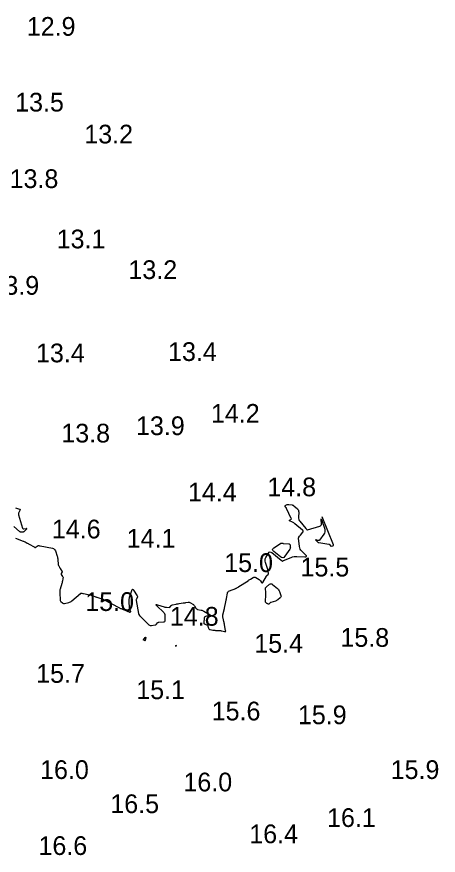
# Model space of a CAD drawing. Extents: x 3040093 to 3056816, y 408076 to 509144.
# Drawn here: x 3044913.4 to 3045025.9, y 434993.4 to 435217.4 of the extents above; entities that cross this region are included whole.
import ezdxf

# ---------------------------------------------------------------- set-up
doc = ezdxf.new("R2010")
doc.units = 0
doc.layers.add('V-CHAN-CONT-EL15', color=7, linetype='Continuous')
doc.layers.add('V-TOPO-SOUN-0810', color=7, linetype='Continuous')

msp = doc.modelspace()

# ---------------------------------------------------------------- linework, layer by layer
at = {"layer": 'V-CHAN-CONT-EL15'}
for points in [[(3044913.02, 435086.15), (3044914.08, 435085.86), (3044914.21, 435085.8), (3044914.27, 435085.72), (3044914.28, 435085.62), (3044914.23, 435085.49), (3044913.9, 435084.93), (3044913.83, 435084.79), (3044913.8, 435084.64), (3044913.8, 435084.49), (3044913.83, 435084.34), (3044914.91, 435080.78), (3044914.97, 435080.66), (3044915.05, 435080.58), (3044915.15, 435080.55), (3044915.29, 435080.56), (3044915.86, 435080.68), (3044915.98, 435080.7), (3044916.03, 435080.67), (3044916.02, 435080.62), (3044915.96, 435080.52), (3044915.4, 435079.87), (3044915.31, 435079.79), (3044915.21, 435079.73), (3044915.11, 435079.7), (3044914.99, 435079.69), (3044914.49, 435079.69), (3044914.38, 435079.7), (3044914.26, 435079.73), (3044914.16, 435079.78), (3044914.07, 435079.85), (3044912.58, 435081.21)], [(3044913.08, 435078.05), (3044915.08, 435077.3), (3044915.21, 435077.25), (3044915.35, 435077.19), (3044915.49, 435077.13), (3044915.62, 435077.06), (3044916.14, 435076.78), (3044916.27, 435076.71), (3044916.4, 435076.64), (3044916.53, 435076.57), (3044916.66, 435076.49), (3044918.06, 435075.72), (3044918.08, 435075.71), (3044918.1, 435075.7), (3044918.12, 435075.69), (3044918.14, 435075.68), (3044918.21, 435075.63), (3044918.22, 435075.62), (3044918.24, 435075.61), (3044918.26, 435075.62), (3044918.28, 435075.62), (3044919.12, 435076.08), (3044919.16, 435076.1), (3044919.2, 435076.11), (3044919.25, 435076.11), (3044919.3, 435076.1), (3044919.48, 435076.05), (3044919.53, 435076.04), (3044919.58, 435076.03), (3044919.62, 435076.02), (3044919.67, 435076.01), (3044922.88, 435075.39), (3044923.17, 435075.3), (3044923.4, 435075.15), (3044923.58, 435074.94), (3044923.71, 435074.66), (3044924.16, 435073.31), (3044924.23, 435073.07), (3044924.29, 435072.83), (3044924.33, 435072.59), (3044924.35, 435072.34), (3044924.45, 435071.06), (3044924.46, 435070.96), (3044924.49, 435070.87), (3044924.52, 435070.78), (3044924.57, 435070.69), (3044924.77, 435070.34), (3044924.82, 435070.26), (3044924.88, 435070.17), (3044924.93, 435070.09), (3044924.98, 435070), (3044925.44, 435069.23), (3044925.47, 435069.15), (3044925.48, 435069.08), (3044925.47, 435069.01), (3044925.43, 435068.94), (3044925.26, 435068.65), (3044925.23, 435068.58), (3044925.22, 435068.51), (3044925.23, 435068.44), (3044925.26, 435068.37), (3044925.63, 435067.82), (3044925.69, 435067.71), (3044925.73, 435067.58), (3044925.74, 435067.46), (3044925.72, 435067.33), (3044925.57, 435066.63), (3044925.54, 435066.47), (3044925.5, 435066.31), (3044925.46, 435066.15), (3044925.41, 435066), (3044924.94, 435064.41), (3044924.92, 435064.31), (3044924.9, 435064.22), (3044924.89, 435064.12), (3044924.89, 435064.03), (3044924.89, 435063.64), (3044924.89, 435063.54), (3044924.9, 435063.45), (3044924.9, 435063.35), (3044924.9, 435063.25), (3044924.95, 435061.67), (3044924.97, 435061.53), (3044925.01, 435061.4), (3044925.08, 435061.28), (3044925.18, 435061.17), (3044925.6, 435060.76), (3044925.71, 435060.67), (3044925.83, 435060.62), (3044925.96, 435060.6), (3044926.1, 435060.62), (3044927.27, 435060.91), (3044927.5, 435060.98), (3044927.72, 435061.08), (3044927.93, 435061.2), (3044928.13, 435061.35), (3044930.4, 435063.32), (3044930.42, 435063.34), (3044930.45, 435063.36), (3044930.48, 435063.37), (3044930.51, 435063.37), (3044930.63, 435063.39), (3044930.66, 435063.39), (3044930.69, 435063.39), (3044930.72, 435063.39), (3044930.75, 435063.38), (3044931.02, 435063.3), (3044931.07, 435063.29), (3044931.13, 435063.27), (3044931.18, 435063.26), (3044931.24, 435063.25), (3044933.22, 435062.81), (3044933.35, 435062.78), (3044933.48, 435062.75), (3044933.61, 435062.71), (3044933.74, 435062.66), (3044934.24, 435062.47), (3044934.37, 435062.43), (3044934.5, 435062.39), (3044934.63, 435062.34), (3044934.76, 435062.3), (3044935.84, 435061.99), (3044936.06, 435061.92), (3044936.28, 435061.84), (3044936.49, 435061.74), (3044936.7, 435061.64), (3044940.65, 435059.53), (3044940.79, 435059.46), (3044940.93, 435059.39), (3044941.08, 435059.33), (3044941.22, 435059.28), (3044941.83, 435059.06), (3044941.97, 435059.02), (3044942.1, 435058.96), (3044942.24, 435058.91), (3044942.37, 435058.85), (3044943.07, 435058.52), (3044943.12, 435058.5), (3044943.16, 435058.48), (3044943.2, 435058.46), (3044943.24, 435058.45), (3044943.41, 435058.38), (3044943.46, 435058.36), (3044943.5, 435058.35), (3044943.55, 435058.35), (3044943.59, 435058.35), (3044943.81, 435058.36), (3044943.85, 435058.37), (3044943.88, 435058.39), (3044943.88, 435058.42), (3044943.87, 435058.46), (3044943.6, 435058.95), (3044943.55, 435059.05), (3044943.52, 435059.16), (3044943.5, 435059.26), (3044943.48, 435059.37), (3044943.39, 435061.28), (3044943.39, 435061.38), (3044943.39, 435061.49), (3044943.4, 435061.6), (3044943.42, 435061.71), (3044943.48, 435062.15), (3044943.5, 435062.25), (3044943.52, 435062.36), (3044943.55, 435062.47), (3044943.58, 435062.57), (3044944.09, 435064.11), (3044944.2, 435064.33), (3044944.32, 435064.41), (3044944.45, 435064.36), (3044944.6, 435064.17), (3044945.55, 435062.64), (3044945.59, 435062.53), (3044945.61, 435062.43), (3044945.6, 435062.33), (3044945.55, 435062.23), (3044945.32, 435061.82), (3044945.27, 435061.72), (3044945.24, 435061.61), (3044945.23, 435061.5), (3044945.25, 435061.39), (3044945.89, 435057.99), (3044945.91, 435057.91), (3044945.93, 435057.83), (3044945.97, 435057.76), (3044946.01, 435057.68), (3044946.18, 435057.4), (3044946.23, 435057.34), (3044946.28, 435057.27), (3044946.33, 435057.21), (3044946.39, 435057.15), (3044948.65, 435054.93), (3044948.81, 435054.81), (3044948.98, 435054.73), (3044949.16, 435054.7), (3044949.36, 435054.71), (3044950.38, 435054.91), (3044950.48, 435054.93), (3044950.57, 435054.98), (3044950.65, 435055.03), (3044950.73, 435055.11), (3044951, 435055.44), (3044951.07, 435055.51), (3044951.15, 435055.57), (3044951.24, 435055.6), (3044951.34, 435055.62), (3044952.57, 435055.7), (3044952.78, 435055.75), (3044952.93, 435055.85), (3044953.01, 435056), (3044953.04, 435056.22), (3044953.01, 435057.33), (3044952.98, 435057.58), (3044952.91, 435057.82), (3044952.79, 435058.03), (3044952.62, 435058.23), (3044950.83, 435059.99), (3044950.65, 435060.2), (3044950.61, 435060.32), (3044950.73, 435060.34), (3044951, 435060.27), (3044952.78, 435059.69), (3044952.93, 435059.65), (3044953.07, 435059.62), (3044953.22, 435059.6), (3044953.36, 435059.6), (3044954.05, 435059.59), (3044954.15, 435059.6), (3044954.24, 435059.63), (3044954.32, 435059.68), (3044954.39, 435059.75), (3044954.64, 435060.06), (3044954.71, 435060.13), (3044954.79, 435060.19), (3044954.88, 435060.23), (3044954.97, 435060.26), (3044955.94, 435060.45), (3044956.13, 435060.49), (3044956.33, 435060.53), (3044956.52, 435060.56), (3044956.72, 435060.59), (3044957.84, 435060.77), (3044958, 435060.79), (3044958.16, 435060.82), (3044958.33, 435060.84), (3044958.49, 435060.87), (3044959.14, 435060.96), (3044959.3, 435060.97), (3044959.45, 435060.95), (3044959.6, 435060.9), (3044959.75, 435060.83), (3044960.42, 435060.42), (3044960.55, 435060.33), (3044960.67, 435060.22), (3044960.78, 435060.1), (3044960.87, 435059.97), (3044961.19, 435059.4), (3044961.29, 435059.27), (3044961.4, 435059.17), (3044961.53, 435059.09), (3044961.68, 435059.05), (3044962.59, 435058.86), (3044962.79, 435058.81), (3044962.99, 435058.74), (3044963.18, 435058.66), (3044963.36, 435058.56), (3044965.07, 435057.55), (3044965.22, 435057.44), (3044965.26, 435057.36), (3044965.19, 435057.31), (3044965, 435057.28), (3044964.02, 435057.23), (3044963.8, 435057.19), (3044963.64, 435057.09), (3044963.53, 435056.93), (3044963.47, 435056.72), (3044963.32, 435055.55), (3044963.32, 435055.42), (3044963.36, 435055.31), (3044963.44, 435055.23), (3044963.55, 435055.17), (3044964.08, 435054.96), (3044964.2, 435054.9), (3044964.3, 435054.81), (3044964.37, 435054.71), (3044964.43, 435054.59), (3044964.61, 435054), (3044964.67, 435053.88), (3044964.76, 435053.78), (3044964.86, 435053.71), (3044965, 435053.66), (3044965.74, 435053.52), (3044965.92, 435053.49), (3044966.09, 435053.47), (3044966.27, 435053.46), (3044966.44, 435053.45), (3044967.47, 435053.42), (3044967.65, 435053.41), (3044967.83, 435053.38), (3044968.01, 435053.35), (3044968.18, 435053.31), (3044968.89, 435053.11), (3044969.04, 435053.09), (3044969.13, 435053.12), (3044969.18, 435053.22), (3044969.17, 435053.37), (3044968.9, 435054.91), (3044968.86, 435055.13), (3044968.81, 435055.35), (3044968.76, 435055.57), (3044968.71, 435055.79), (3044968.47, 435056.67), (3044968.42, 435056.89), (3044968.41, 435057.11), (3044968.41, 435057.33), (3044968.45, 435057.55), (3044968.83, 435059.32), (3044968.88, 435059.55), (3044968.92, 435059.77), (3044968.97, 435060), (3044969.02, 435060.22), (3044969.27, 435061.51), (3044969.28, 435061.55), (3044969.29, 435061.58), (3044969.3, 435061.62), (3044969.31, 435061.65), (3044969.36, 435061.79), (3044969.37, 435061.83), (3044969.38, 435061.86), (3044969.39, 435061.9), (3044969.4, 435061.93), (3044969.62, 435063.34), (3044969.68, 435063.56), (3044969.8, 435063.75), (3044969.96, 435063.9), (3044970.17, 435064.01), (3044971.88, 435064.67), (3044971.9, 435064.67), (3044971.92, 435064.68), (3044971.95, 435064.69), (3044971.97, 435064.7), (3044972.06, 435064.74), (3044972.08, 435064.75), (3044972.1, 435064.76), (3044972.12, 435064.77), (3044972.14, 435064.79), (3044972.48, 435064.98), (3044972.55, 435065.02), (3044972.61, 435065.05), (3044972.67, 435065.09), (3044972.73, 435065.13), (3044975.14, 435066.72), (3044975.31, 435066.83), (3044975.48, 435066.94), (3044975.65, 435067.05), (3044975.82, 435067.15), (3044976.51, 435067.58), (3044976.68, 435067.66), (3044976.86, 435067.68), (3044977.03, 435067.66), (3044977.2, 435067.58), (3044978.08, 435067.04), (3044978.19, 435066.96), (3044978.29, 435066.87), (3044978.39, 435066.78), (3044978.47, 435066.67), (3044978.78, 435066.21), (3044978.85, 435066.13), (3044978.93, 435066.1), (3044979, 435066.13), (3044979.07, 435066.22), (3044980.08, 435067.96), (3044980.12, 435068.02), (3044980.17, 435068.08), (3044980.22, 435068.13), (3044980.27, 435068.18), (3044980.51, 435068.37), (3044980.56, 435068.42), (3044980.59, 435068.47), (3044980.6, 435068.52), (3044980.6, 435068.59), (3044980.57, 435068.89), (3044980.56, 435068.94), (3044980.56, 435068.99), (3044980.55, 435069.03), (3044980.55, 435069.08), (3044980.52, 435069.26), (3044980.52, 435069.3), (3044980.51, 435069.35), (3044980.5, 435069.39), (3044980.48, 435069.43), (3044979.77, 435071.62), (3044979.69, 435071.95), (3044979.69, 435072.27), (3044979.76, 435072.57), (3044979.91, 435072.88), (3044980.62, 435074.06), (3044980.81, 435074.3), (3044981.02, 435074.4), (3044981.26, 435074.37), (3044981.51, 435074.22), (3044983.96, 435072.2), (3044983.99, 435072.17), (3044984.02, 435072.15), (3044984.06, 435072.12), (3044984.09, 435072.1), (3044984.26, 435071.98), (3044984.27, 435071.97), (3044984.29, 435071.97), (3044984.3, 435071.96), (3044984.32, 435071.97), (3044984.39, 435071.98), (3044984.41, 435071.98), (3044984.42, 435071.99), (3044984.44, 435071.99), (3044984.45, 435072), (3044984.52, 435072.06), (3044984.54, 435072.07), (3044984.56, 435072.08), (3044984.58, 435072.09), (3044984.6, 435072.1), (3044986.7, 435072.95), (3044987.06, 435073.07), (3044987.43, 435073.16), (3044987.8, 435073.2), (3044988.19, 435073.2), (3044990.34, 435073.09), (3044990.62, 435073.1), (3044990.75, 435073.19), (3044990.73, 435073.34), (3044990.54, 435073.56), (3044989.49, 435074.58), (3044989.25, 435074.85), (3044989.08, 435075.14), (3044988.95, 435075.47), (3044988.89, 435075.82), (3044988.66, 435078.1), (3044988.65, 435078.18), (3044988.67, 435078.25), (3044988.69, 435078.31), (3044988.74, 435078.38), (3044988.93, 435078.62), (3044988.97, 435078.68), (3044989.02, 435078.74), (3044989.07, 435078.8), (3044989.12, 435078.86), (3044989.77, 435079.66), (3044989.86, 435079.81), (3044989.88, 435079.96), (3044989.83, 435080.09), (3044989.71, 435080.22), (3044987.65, 435081.94), (3044987.51, 435082.05), (3044987.36, 435082.15), (3044987.21, 435082.24), (3044987.05, 435082.32), (3044986.26, 435082.69), (3044986.19, 435082.73), (3044986.17, 435082.78), (3044986.19, 435082.83), (3044986.25, 435082.88), (3044986.6, 435083.08), (3044986.68, 435083.14), (3044986.71, 435083.21), (3044986.72, 435083.28), (3044986.69, 435083.37), (3044985.46, 435086.04), (3044985.43, 435086.08), (3044985.41, 435086.12), (3044985.38, 435086.15), (3044985.34, 435086.18), (3044985.2, 435086.3), (3044985.17, 435086.33), (3044985.14, 435086.36), (3044985.12, 435086.4), (3044985.1, 435086.44), (3044985.02, 435086.68), (3044985.01, 435086.7), (3044985.01, 435086.72), (3044985.03, 435086.73), (3044985.04, 435086.75), (3044985.13, 435086.8), (3044985.16, 435086.81), (3044985.18, 435086.83), (3044985.2, 435086.84), (3044985.22, 435086.85), (3044985.6, 435087.04), (3044985.63, 435087.06), (3044985.67, 435087.07), (3044985.71, 435087.07), (3044985.75, 435087.07), (3044985.91, 435087.06), (3044985.95, 435087.05), (3044985.99, 435087.05), (3044986.03, 435087.04), (3044986.07, 435087.04), (3044986.9, 435086.95), (3044987.04, 435086.92), (3044987.18, 435086.88), (3044987.3, 435086.81), (3044987.42, 435086.71), (3044988.32, 435085.9), (3044988.48, 435085.72), (3044988.59, 435085.52), (3044988.66, 435085.3), (3044988.67, 435085.05), (3044988.64, 435083.69), (3044988.66, 435083.39), (3044988.72, 435083.1), (3044988.84, 435082.84), (3044989.02, 435082.59), (3044990.61, 435080.64), (3044990.64, 435080.61), (3044990.67, 435080.57), (3044990.7, 435080.53), (3044990.73, 435080.5), (3044990.86, 435080.36), (3044990.89, 435080.33), (3044990.93, 435080.31), (3044990.97, 435080.31), (3044991.01, 435080.31), (3044994.3, 435081.26), (3044994.52, 435081.36), (3044994.67, 435081.51), (3044994.75, 435081.7), (3044994.76, 435081.94), (3044994.67, 435083.01), (3044994.66, 435083.21), (3044994.67, 435083.28), (3044994.72, 435083.22), (3044994.79, 435083.03), (3044995.63, 435080.45), (3044995.7, 435080.1), (3044995.69, 435079.77), (3044995.59, 435079.45), (3044995.41, 435079.15), (3044994.23, 435077.57), (3044994.15, 435077.49), (3044994.05, 435077.44), (3044993.94, 435077.43), (3044993.83, 435077.45), (3044993.33, 435077.63), (3044993.23, 435077.65), (3044993.19, 435077.65), (3044993.2, 435077.61), (3044993.27, 435077.53), (3044993.87, 435076.95), (3044993.88, 435076.94), (3044993.89, 435076.93), (3044993.9, 435076.93), (3044993.91, 435076.92), (3044993.96, 435076.92), (3044993.98, 435076.91), (3044993.99, 435076.91), (3044994, 435076.91), (3044994.01, 435076.91), (3044996.73, 435076.45), (3044996.8, 435076.43), (3044996.86, 435076.4), (3044996.92, 435076.36), (3044996.96, 435076.3), (3044997.13, 435076.05), (3044997.18, 435076), (3044997.23, 435075.97), (3044997.29, 435075.95), (3044997.36, 435075.96), (3044997.81, 435076.05), (3044997.89, 435076.08), (3044997.94, 435076.13), (3044997.95, 435076.2), (3044997.93, 435076.28), (3044994.96, 435083.81)]]:
    msp.add_lwpolyline(points, dxfattribs=at)
for points in [[(3044986.45, 435075.55), (3044986.43, 435075.41), (3044986.38, 435075.28), (3044986.31, 435075.15), (3044984.96, 435073.23), (3044984.7, 435072.95), (3044984.41, 435072.83), (3044984.11, 435072.87), (3044983.78, 435073.07), (3044982, 435074.53), (3044981.78, 435074.77), (3044981.72, 435075), (3044981.8, 435075.23), (3044982.04, 435075.45), (3044983.81, 435076.67), (3044983.87, 435076.7), (3044983.92, 435076.72), (3044983.98, 435076.73), (3044984.04, 435076.73), (3044984.28, 435076.71), (3044984.34, 435076.7), (3044984.41, 435076.7), (3044984.47, 435076.7), (3044984.53, 435076.69), (3044986.03, 435076.6), (3044986.16, 435076.57), (3044986.26, 435076.51), (3044986.33, 435076.42), (3044986.37, 435076.29), (3044986.44, 435075.69)], [(3044982.96, 435061.53), (3044982.79, 435061.43), (3044982.62, 435061.35), (3044982.44, 435061.28), (3044981.25, 435060.88), (3044981.18, 435060.85), (3044981.11, 435060.81), (3044981.05, 435060.77), (3044980.99, 435060.72), (3044980.74, 435060.45), (3044980.7, 435060.42), (3044980.66, 435060.41), (3044980.62, 435060.41), (3044980.57, 435060.43), (3044980.39, 435060.52), (3044980.34, 435060.55), (3044980.3, 435060.57), (3044980.25, 435060.6), (3044980.21, 435060.63), (3044979.95, 435060.81), (3044979.9, 435060.85), (3044979.86, 435060.9), (3044979.84, 435060.96), (3044979.83, 435061.03), (3044979.89, 435063.05), (3044979.89, 435063.23), (3044979.89, 435063.41), (3044979.88, 435063.58), (3044979.86, 435063.76), (3044979.78, 435064.46), (3044979.78, 435064.62), (3044979.82, 435064.78), (3044979.9, 435064.91), (3044980.01, 435065.03), (3044980.91, 435065.75), (3044981.11, 435065.87), (3044981.3, 435065.9), (3044981.49, 435065.86), (3044981.68, 435065.74), (3044982.98, 435064.62), (3044983.16, 435064.44), (3044983.31, 435064.25), (3044983.43, 435064.03), (3044983.53, 435063.8), (3044983.91, 435062.72), (3044983.95, 435062.54), (3044983.93, 435062.38), (3044983.86, 435062.24), (3044983.73, 435062.12), (3044983.11, 435061.64)], [(3044947.61, 435050.67), (3044947.6, 435050.66), (3044947.59, 435050.66), (3044947.58, 435050.67), (3044947.52, 435050.71), (3044947.51, 435050.72), (3044947.49, 435050.73), (3044947.48, 435050.74), (3044947.46, 435050.75), (3044947.28, 435050.85), (3044947.25, 435050.87), (3044947.23, 435050.9), (3044947.24, 435050.92), (3044947.25, 435050.95), (3044947.71, 435051.52), (3044947.77, 435051.59), (3044947.8, 435051.6), (3044947.82, 435051.57), (3044947.81, 435051.48), (3044947.67, 435050.83), (3044947.67, 435050.81), (3044947.66, 435050.8), (3044947.66, 435050.78), (3044947.65, 435050.76), (3044947.62, 435050.68)], [(3044956.02, 435049.41), (3044956.03, 435049.4), (3044956.03, 435049.39), (3044956.02, 435049.38), (3044955.9, 435049.19), (3044955.89, 435049.18), (3044955.88, 435049.17), (3044955.87, 435049.18), (3044955.87, 435049.2), (3044955.86, 435049.31), (3044955.86, 435049.32), (3044955.86, 435049.33), (3044955.86, 435049.34), (3044955.86, 435049.36), (3044955.89, 435049.42), (3044955.9, 435049.42), (3044955.9, 435049.43), (3044955.9, 435049.43), (3044955.91, 435049.44), (3044955.93, 435049.45), (3044955.93, 435049.46), (3044955.94, 435049.46), (3044955.94, 435049.46), (3044955.95, 435049.46), (3044956.01, 435049.42)]]:
    msp.add_lwpolyline(points, close=True, dxfattribs=at)

# ---------------------------------------------------------------- texts
at = {"layer": 'V-TOPO-SOUN-0810'}
for s, p in [('12.9 ', (3044916.06, 435212.3)), ('13.5 ', (3044912.95, 435192.06)), ('13.2 ', (3044931.42, 435183.53)), ('13.8 ', (3044911.47, 435171.62)), ('13.1 ', (3044924.04, 435155.51)), ('13.2 ', (3044943.2, 435147.31)), ('13.9 ', (3044906.35, 435143.11)), ('13.4 ', (3044918.52, 435125.06)), ('13.4 ', (3044953.79, 435125.42)), ('14.2 ', (3044965.24, 435108.92)), ('13.9 ', (3044945.23, 435105.61)), ('13.8 ', (3044925.28, 435103.64)), ('14.4 ', (3044959.11, 435087.89)), ('14.8 ', (3044980.3, 435089.27)), ('14.6 ', (3044922.76, 435078.01)), ('14.1 ', (3044942.74, 435075.55)), ('15.0 ', (3044968.79, 435069.03)), ('15.5 ', (3044989.16, 435067.84)), ('15.0 ', (3044931.68, 435058.63)), ('14.8 ', (3044954.28, 435054.69)), ('15.4 ', (3044976.82, 435047.47)), ('15.8 ', (3044999.82, 435049.05)), ('15.7 ', (3044918.56, 435039.43)), ('15.1 ', (3044945.3, 435035.07)), ('15.6 ', (3044965.44, 435029.39)), ('15.9 ', (3044988.47, 435028.38)), ('16.0 ', (3044919.61, 435013.74)), ('15.9 ', (3045013.24, 435013.74)), ('16.0 ', (3044957.89, 435010.43)), ('16.5 ', (3044938.37, 435004.62)), ('16.1 ', (3044996.25, 435000.92)), ('16.4 ', (3044975.48, 434996.58)), ('16.6 ', (3044919.18, 434993.44))]:
    msp.add_text(s, height=5, dxfattribs=at).set_placement(p)

doc.saveas('drawing.dxf')
